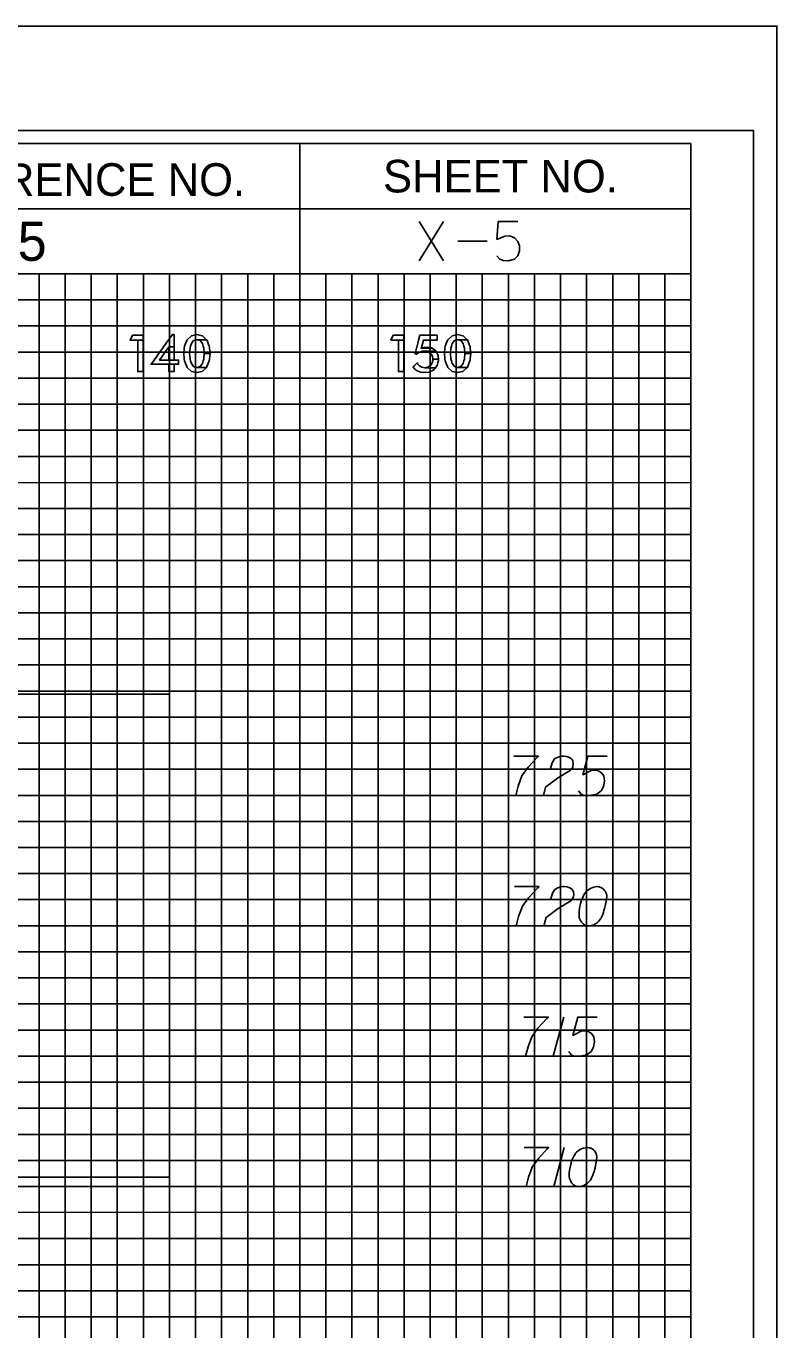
# Model space of a CAD drawing. Extents: x -13 to 323, y -5 to 1431.
# Drawn here: x 294.5 to 323.3, y 824.5 to 874.5 of the extents above; entities that cross this region are included whole.
import ezdxf

# ---------------------------------------------------------------- set-up
doc = ezdxf.new("R2010")
doc.units = 0
for name, color, linetype in [('Prop XS Elevation Labels', 7, 'Continuous'), ('Prop XS Offset Labels', 7, 'Continuous'), ('Prop XS Project Number', 7, 'Continuous'), ('Prop XS Sheet Number', 7, 'Continuous'), ('Scratch_Level_3', 7, 'Continuous'), ('Sheet Cross Section CELL', 7, 'Continuous'), ('Sheet Cross Section Grid Major CELL', 7, 'Continuous'), ('Sheet Cross Section Grid Middle CELL', 7, 'Continuous'), ('Sheet Cross Section Grid Minor 1 CELL', 7, 'Continuous'), ('Sheet Cross Section Grid Minor 2 CELL', 7, 'Continuous'), ('Sheet Cutting Line CELL', 7, 'Continuous'), ('Sheet DOT Grid CELL', 7, 'Continuous'), ('Sheet Plot Border Inside CELL', 7, 'Continuous'), ('Sheet Plot Border Outside CELL', 7, 'Continuous')]:
    doc.layers.add(name, color=color, linetype=linetype)

msp = doc.modelspace()

# ---------------------------------------------------------------- linework, layer by layer
at = {"layer": 'Prop XS Elevation Labels'}
for p, q in [((315.124, 836.5), (314.723, 835)), ((315.142, 831.5), (314.74, 830))]:
    msp.add_line(p, q, dxfattribs=at)
for points in [[(313.211, 846.5), (314.155, 846.5), (314.096, 846.441), (313.754, 846.075), (313.518, 845.744), (313.376, 845.354), (313.281, 845)], [(314.616, 846.028), (314.675, 846.252), (314.77, 846.394), (314.876, 846.453), (314.982, 846.488), (315.065, 846.5), (315.124, 846.5), (315.23, 846.488), (315.301, 846.465), (315.337, 846.453), (315.408, 846.417), (315.443, 846.37), (315.467, 846.323), (315.478, 846.287), (315.49, 846.24), (315.49, 846.181), (315.478, 846.122), (315.467, 846.087), (315.443, 846.039), (315.408, 845.992), (315.372, 845.957), (314.888, 845.661), (314.427, 845.319), (314.345, 845), (315.419, 845)], [(316.789, 846.5), (316.045, 846.5), (315.856, 845.791), (316.199, 845.969), (316.4, 845.969), (316.565, 845.862), (316.66, 845.744), (316.683, 845.543), (316.648, 845.342), (316.553, 845.177), (316.388, 845.047), (316.104, 845), (315.892, 845), (315.785, 845.047), (315.691, 845.177)], [(313.228, 841.5), (314.173, 841.5), (314.114, 841.441), (313.772, 841.075), (313.535, 840.744), (313.394, 840.354), (313.299, 840)], [(314.634, 841.028), (314.693, 841.252), (314.787, 841.394), (314.894, 841.453), (315, 841.488), (315.083, 841.5), (315.142, 841.5), (315.248, 841.488), (315.319, 841.465), (315.354, 841.453), (315.425, 841.417), (315.461, 841.37), (315.484, 841.323), (315.496, 841.287), (315.508, 841.24), (315.508, 841.181), (315.496, 841.122), (315.484, 841.087), (315.461, 841.039), (315.425, 840.992), (315.39, 840.957), (314.906, 840.661), (314.445, 840.319), (314.362, 840), (315.437, 840)], [(316.417, 841.5), (316.394, 841.5), (316.323, 841.488), (316.276, 841.476), (316.24, 841.465), (316.181, 841.441), (316.11, 841.406), (316.051, 841.37), (315.992, 841.323), (315.957, 841.276), (315.921, 841.217), (315.886, 841.158), (315.85, 841.087), (315.827, 841.039), (315.803, 840.969), (315.768, 840.85), (315.732, 840.673), (315.709, 840.531), (315.709, 840.402), (315.721, 840.307), (315.768, 840.201), (315.803, 840.142), (315.862, 840.071), (315.933, 840.024), (315.968, 840.012), (316.039, 840), (316.098, 840), (316.193, 840.012), (316.276, 840.035), (316.335, 840.071), (316.417, 840.13), (316.453, 840.165), (316.5, 840.213), (316.535, 840.26), (316.559, 840.295), (316.583, 840.354), (316.594, 840.378), (316.618, 840.437), (316.642, 840.508), (316.665, 840.579), (316.677, 840.626), (316.689, 840.661), (316.701, 840.709), (316.724, 840.815), (316.736, 840.874), (316.748, 840.933), (316.76, 841.016), (316.772, 841.122), (316.772, 841.158), (316.76, 841.205), (316.748, 841.252), (316.713, 841.323), (316.677, 841.37), (316.642, 841.406), (316.594, 841.441), (316.547, 841.465), (316.512, 841.476), (316.476, 841.488), (316.417, 841.5)], [(313.589, 836.5), (314.533, 836.5), (314.474, 836.441), (314.132, 836.075), (313.896, 835.744), (313.754, 835.354), (313.659, 835)], [(316.411, 836.5), (315.667, 836.5), (315.478, 835.791), (315.821, 835.969), (316.022, 835.969), (316.187, 835.862), (316.282, 835.744), (316.305, 835.543), (316.27, 835.342), (316.175, 835.177), (316.01, 835.047), (315.726, 835), (315.514, 835), (315.408, 835.047), (315.313, 835.177)], [(313.606, 831.5), (314.551, 831.5), (314.492, 831.441), (314.149, 831.075), (313.913, 830.744), (313.772, 830.354), (313.677, 830)], [(316.039, 831.5), (316.016, 831.5), (315.945, 831.488), (315.898, 831.476), (315.862, 831.465), (315.803, 831.441), (315.732, 831.406), (315.673, 831.37), (315.614, 831.323), (315.579, 831.276), (315.543, 831.217), (315.508, 831.158), (315.472, 831.087), (315.449, 831.039), (315.425, 830.969), (315.39, 830.85), (315.354, 830.673), (315.331, 830.531), (315.331, 830.402), (315.343, 830.307), (315.39, 830.201), (315.425, 830.142), (315.484, 830.071), (315.555, 830.024), (315.591, 830.012), (315.661, 830), (315.72, 830), (315.815, 830.012), (315.898, 830.035), (315.957, 830.071), (316.039, 830.13), (316.075, 830.165), (316.122, 830.213), (316.157, 830.26), (316.181, 830.295), (316.205, 830.354), (316.217, 830.378), (316.24, 830.437), (316.264, 830.508), (316.287, 830.579), (316.299, 830.626), (316.311, 830.661), (316.323, 830.709), (316.347, 830.815), (316.358, 830.874), (316.37, 830.933), (316.382, 831.016), (316.394, 831.122), (316.394, 831.158), (316.382, 831.205), (316.37, 831.252), (316.335, 831.323), (316.299, 831.37), (316.264, 831.406), (316.217, 831.441), (316.169, 831.465), (316.134, 831.476), (316.098, 831.488), (316.039, 831.5)]]:
    msp.add_lwpolyline(points, dxfattribs=at)
at = {"layer": 'Prop XS Offset Labels'}
for points in [[(298.581, 862.641), (298.492, 862.459), (298.99, 862.459), (298.99, 862.641)], [(299.411, 861.693), (299.297, 861.534), (300.35, 861.534), (300.35, 861.693), (299.618, 861.693), (299.878, 862.059), (299.935, 862.139), (299.977, 862.199), (300.179, 862.199), (300.179, 862.668), (300.114, 862.668), (299.775, 862.199), (299.733, 862.139), (299.675, 862.059)], [(300.851, 861.255), (301.051, 861.214), (301.245, 861.255), (301.256, 861.257), (301.422, 861.409), (301.048, 861.409), (301.038, 861.411), (301.033, 861.413), (300.928, 861.442), (300.841, 861.555), (300.841, 861.556), (300.841, 861.556), (300.813, 861.657), (300.813, 861.659), (300.793, 861.732), (300.792, 861.736), (300.774, 861.939), (300.774, 861.941), (300.774, 861.943), (300.792, 862.145), (300.812, 862.222), (300.813, 862.224), (300.839, 862.322), (300.84, 862.325), (300.928, 862.44), (301.041, 862.469), (301.045, 862.47), (301.055, 862.473), (301.425, 862.473), (301.262, 862.622), (301.254, 862.624), (301.053, 862.668), (301.053, 862.668), (300.845, 862.624), (300.843, 862.622), (300.681, 862.473), (300.678, 862.47), (300.678, 862.469), (300.665, 862.44), (300.618, 862.325), (300.617, 862.322), (300.577, 862.224), (300.576, 862.222), (300.568, 862.145), (300.547, 861.943), (300.547, 861.941), (300.547, 861.939), (300.567, 861.736), (300.567, 861.732), (300.575, 861.659), (300.575, 861.657), (300.616, 861.556), (300.617, 861.555), (300.663, 861.442), (300.675, 861.413), (300.676, 861.411), (300.679, 861.409), (300.848, 861.257)], [(308.581, 862.641), (308.492, 862.459), (308.99, 862.459), (308.99, 862.641)], [(309.427, 861.94), (309.424, 861.928), (309.495, 861.928), (309.508, 861.94), (309.524, 861.954), (309.595, 861.997), (309.627, 862.007), (309.697, 862.029), (309.811, 862.035), (310.219, 862.035), (310.211, 862.05), (310.076, 862.145), (309.655, 862.145), (309.658, 862.158), (309.658, 862.158), (309.663, 862.178), (309.738, 862.456), (310.263, 862.456), (310.263, 862.641), (309.6, 862.641), (309.554, 862.456), (309.486, 862.178), (309.481, 862.158), (309.478, 862.145), (309.454, 862.05), (309.451, 862.035), (309.449, 862.029), (309.444, 862.007), (309.441, 861.997), (309.431, 861.954)], [(310.851, 861.255), (311.051, 861.214), (311.245, 861.255), (311.256, 861.257), (311.422, 861.409), (311.048, 861.409), (311.038, 861.411), (311.033, 861.413), (310.928, 861.442), (310.841, 861.555), (310.841, 861.556), (310.841, 861.556), (310.813, 861.657), (310.813, 861.659), (310.793, 861.732), (310.792, 861.736), (310.774, 861.939), (310.774, 861.941), (310.774, 861.943), (310.792, 862.145), (310.812, 862.222), (310.813, 862.224), (310.839, 862.322), (310.84, 862.325), (310.928, 862.44), (311.041, 862.469), (311.045, 862.47), (311.055, 862.473), (311.425, 862.473), (311.262, 862.622), (311.254, 862.624), (311.053, 862.668), (311.053, 862.668), (310.845, 862.624), (310.843, 862.622), (310.681, 862.473), (310.678, 862.47), (310.678, 862.469), (310.665, 862.44), (310.618, 862.325), (310.617, 862.322), (310.577, 862.224), (310.576, 862.222), (310.568, 862.145), (310.547, 861.943), (310.547, 861.941), (310.547, 861.939), (310.567, 861.736), (310.567, 861.732), (310.575, 861.659), (310.575, 861.657), (310.616, 861.556), (310.617, 861.555), (310.663, 861.442), (310.675, 861.413), (310.676, 861.411), (310.679, 861.409), (310.848, 861.257)], [(298.781, 862.459), (298.781, 861.25), (298.99, 861.25), (298.99, 862.459)], [(299.97, 862.059), (299.97, 861.693), (300.179, 861.693), (300.179, 862.059), (300.179, 862.139), (300.179, 862.199), (299.977, 862.199), (299.973, 862.139)], [(301.312, 862.145), (301.328, 861.943), (301.555, 861.943), (301.536, 862.145), (301.528, 862.222), (301.528, 862.224), (301.527, 862.224), (301.488, 862.322), (301.488, 862.322), (301.487, 862.325), (301.441, 862.44), (301.44, 862.44), (301.429, 862.469), (301.428, 862.47), (301.425, 862.473), (301.055, 862.473), (301.065, 862.47), (301.068, 862.469), (301.175, 862.44), (301.262, 862.325), (301.265, 862.322), (301.291, 862.224), (301.291, 862.222)], [(308.781, 862.459), (308.781, 861.25), (308.99, 861.25), (308.99, 862.459)], [(309.692, 862.158), (309.655, 862.145), (310.076, 862.145), (310.058, 862.158), (309.961, 862.178), (309.75, 862.178)], [(309.888, 862.192), (309.75, 862.178), (309.96, 862.178), (309.888, 862.192)], [(310.083, 861.841), (310.105, 861.721), (310.318, 861.721), (310.307, 861.841), (310.307, 861.841), (310.303, 861.881), (310.284, 861.916), (310.278, 861.928), (310.271, 861.94), (310.263, 861.954), (310.24, 861.997), (310.235, 862.007), (310.223, 862.029), (310.219, 862.035), (309.811, 862.035), (309.838, 862.029), (309.928, 862.007), (309.942, 861.997), (310.003, 861.954), (310.024, 861.94), (310.031, 861.928), (310.038, 861.916), (310.059, 861.881)], [(311.312, 862.145), (311.328, 861.943), (311.555, 861.943), (311.536, 862.145), (311.528, 862.222), (311.528, 862.224), (311.527, 862.224), (311.488, 862.322), (311.488, 862.322), (311.487, 862.325), (311.441, 862.44), (311.44, 862.44), (311.429, 862.469), (311.428, 862.47), (311.425, 862.473), (311.055, 862.473), (311.065, 862.47), (311.068, 862.469), (311.175, 862.44), (311.262, 862.325), (311.265, 862.322), (311.291, 862.224), (311.291, 862.222)], [(299.97, 861.534), (299.97, 861.25), (300.179, 861.25), (300.179, 861.534)], [(301.058, 861.411), (301.048, 861.409), (301.422, 861.409), (301.425, 861.411), (301.426, 861.413), (301.438, 861.442), (301.485, 861.555), (301.485, 861.556), (301.527, 861.657), (301.528, 861.659), (301.535, 861.732), (301.535, 861.736), (301.555, 861.939), (301.556, 861.941), (301.555, 861.943), (301.328, 861.943), (301.328, 861.941), (301.328, 861.939), (301.312, 861.736), (301.312, 861.732), (301.292, 861.659), (301.291, 861.657), (301.264, 861.556), (301.263, 861.555), (301.175, 861.442), (301.063, 861.413)], [(309.626, 861.233), (309.762, 861.214), (309.959, 861.233), (309.968, 861.237), (310.091, 861.297), (310.091, 861.297), (310.141, 861.321), (310.185, 861.375), (310.204, 861.399), (309.793, 861.399), (309.683, 861.418), (309.682, 861.419), (309.679, 861.42), (309.596, 861.466), (309.586, 861.477), (309.58, 861.483), (309.58, 861.483), (309.529, 861.535), (309.497, 861.585), (309.497, 861.585), (309.451, 861.535), (309.404, 861.483), (309.399, 861.477), (309.39, 861.466), (309.348, 861.42), (309.347, 861.419), (309.348, 861.418), (309.363, 861.399), (309.382, 861.375), (309.445, 861.321), (309.474, 861.297), (309.598, 861.237)], [(309.424, 861.928), (309.482, 861.916), (309.495, 861.928)], [(309.9, 861.418), (309.793, 861.399), (310.204, 861.399), (310.22, 861.418), (310.221, 861.419), (310.222, 861.42), (310.222, 861.42), (310.259, 861.466), (310.268, 861.477), (310.27, 861.483), (310.284, 861.535), (310.299, 861.59), (310.322, 861.674), (310.318, 861.721), (310.105, 861.721), (310.097, 861.674), (310.082, 861.59), (310.047, 861.535), (310.014, 861.483), (310.004, 861.477), (309.987, 861.466), (309.913, 861.42), (309.905, 861.419)], [(311.058, 861.411), (311.048, 861.409), (311.422, 861.409), (311.425, 861.411), (311.426, 861.413), (311.438, 861.442), (311.485, 861.555), (311.485, 861.556), (311.527, 861.657), (311.528, 861.659), (311.535, 861.732), (311.535, 861.736), (311.555, 861.939), (311.556, 861.941), (311.555, 861.943), (311.328, 861.943), (311.328, 861.941), (311.328, 861.939), (311.312, 861.736), (311.312, 861.732), (311.292, 861.659), (311.291, 861.657), (311.264, 861.556), (311.263, 861.555), (311.175, 861.442), (311.063, 861.413)]]:
    msp.add_lwpolyline(points, close=True, dxfattribs=at)
at = {"layer": 'Prop XS Sheet Number'}
for p, q in [((309.575, 867), (310.508, 865.5)), ((310.508, 867), (309.575, 865.5)), ((311.063, 866.256), (312.185, 866.256))]:
    msp.add_line(p, q, dxfattribs=at)
for points in [[(313.366, 867), (312.61, 867), (312.551, 866.315)], [(312.551, 866.315), (312.858, 866.445), (313.059, 866.457), (313.236, 866.374), (313.366, 866.244), (313.425, 866.067), (313.425, 865.961), (313.425, 865.878), (313.366, 865.689), (313.236, 865.559), (312.988, 865.5), (312.799, 865.512), (312.669, 865.559), (312.551, 865.689)]]:
    msp.add_lwpolyline(points, dxfattribs=at)
at = {"layer": 'Scratch_Level_3'}
msp.add_lwpolyline([(20, 848.886), (300, 848.886), (300, 830.355), (20, 830.355)], close=True, dxfattribs=at)
at = {"layer": 'Sheet Cross Section CELL'}
for p, q in [((305, 870), (305, 865)), ((305, 865), (305, 870)), ((320, 867.49), (280, 867.49)), ((280, 865), (320, 865))]:
    msp.add_line(p, q, dxfattribs=at)
for points in [[(320, 870), (0, 870), (0, 660), (320, 660)], [(320, 870), (280, 870), (280, 865), (320, 865)]]:
    msp.add_lwpolyline(points, close=True, dxfattribs=at)
at = {"layer": 'Sheet Cross Section Grid Major CELL'}
for p, q in [((310, 865), (300, 865)), ((300, 865), (300, 660)), ((310, 660), (310, 865))]:
    msp.add_line(p, q, dxfattribs=at)
for points in [[(0, 860), (320, 860), (320, 850), (0, 850)], [(0, 840), (320, 840), (320, 830), (0, 830)]]:
    msp.add_lwpolyline(points, dxfattribs=at)
at = {"layer": 'Sheet Cross Section Grid Middle CELL'}
for points in [[(295, 660), (295, 865), (305, 865), (305, 660)], [(315, 660), (315, 865)], [(0, 845), (320, 845), (320, 855), (0, 855)], [(0, 825), (320, 825), (320, 835), (0, 835)]]:
    msp.add_lwpolyline(points, dxfattribs=at)
at = {"layer": 'Sheet Cross Section Grid Minor 1 CELL'}
msp.add_line((0, 864), (320, 864), dxfattribs=at)
for points in [[(0, 863), (270, 863), (320, 863), (320, 862), (0, 862)], [(0, 861), (320, 861), (320, 859), (0, 859)], [(0, 858), (320, 858), (320, 857), (0, 856.98)], [(0, 856), (320, 856), (320, 854), (0, 854)], [(0, 853), (320, 853), (320, 852), (0, 852)], [(0, 851), (320, 851), (320, 849), (0, 849)], [(0, 848), (320, 848), (320, 847), (0, 847)], [(0, 846), (320, 846), (320, 844), (0, 844)], [(0, 843), (320, 843), (320, 842), (0, 842)], [(0, 841), (320, 841), (320, 839), (0, 839)], [(0, 838), (320, 838), (320, 837), (0, 837)], [(0, 836), (320, 836), (320, 833.95), (320, 833), (320, 832), (0, 832)], [(0, 834), (320, 834), (320, 833), (0, 833)], [(0, 831), (320, 831), (320, 829), (0, 829.03)], [(0, 829.03), (320, 829), (320, 828), (0, 828)], [(0, 827), (320, 827), (320, 826), (0, 826)]]:
    msp.add_lwpolyline(points, dxfattribs=at)
at = {"layer": 'Sheet Cross Section Grid Minor 2 CELL'}
for points in [[(295, 660), (296, 660), (296, 865), (297, 865), (297, 660)], [(297, 660), (298, 660), (298, 865), (299, 865), (299, 660)], [(300, 660), (301, 660), (301, 865), (302, 865), (302, 660)], [(302, 660), (303, 660), (303, 865), (304, 865), (304, 660)], [(305, 660), (306, 660), (306, 865), (307, 865), (307, 660)], [(307, 660), (308, 660), (308, 865), (309, 865), (309, 660)], [(310, 660), (311, 660), (311, 865), (312, 865), (312, 660)], [(312, 660), (313, 660), (313, 865), (314, 865), (314, 660)], [(315, 660), (316, 660), (316, 865), (317, 865), (317, 660)], [(317, 660), (318, 660), (318, 865), (319, 865), (319, 660)]]:
    msp.add_lwpolyline(points, dxfattribs=at)
at = {"layer": 'Sheet Cutting Line CELL'}
msp.add_line((323.3, 874.5), (-13.4, 874.5), dxfattribs=at)
at = {"layer": 'Sheet DOT Grid CELL'}
for p, q in [((300, 660), (300, 864.687)), ((310, 660), (310, 864.687)), ((0, 860), (320, 860)), ((0, 850), (320, 850)), ((0, 840), (320, 840)), ((0, 830), (320, 830))]:
    msp.add_line(p, q, dxfattribs=at)
at = {"layer": 'Sheet Plot Border Inside CELL'}
msp.add_lwpolyline([(-10.8, 659.5), (322.4, 659.5), (322.4, 870.5), (-10.8, 870.5)], close=True, dxfattribs=at)
at = {"layer": 'Sheet Plot Border Outside CELL'}
msp.add_lwpolyline([(-13.4, 655.5), (323.3, 655.5), (323.3, 874.5), (-13.4, 874.5)], close=True, dxfattribs=at)

# ---------------------------------------------------------------- texts
at = {"layer": 'Prop XS Project Number'}
msp.add_text('HL-0025', height=1.5, dxfattribs=at).set_placement((287.598, 865.5))
at = {"layer": 'Sheet Cross Section CELL'}
for s, height, p in [('PROJ. REFERENCE NO.', 1.24998, (283.77, 867.99)), ('SHEET NO.', 1.25, (308.19, 868.12))]:
    msp.add_text(s, height=height, dxfattribs=at).set_placement(p)

doc.saveas('drawing.dxf')
